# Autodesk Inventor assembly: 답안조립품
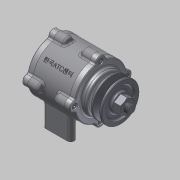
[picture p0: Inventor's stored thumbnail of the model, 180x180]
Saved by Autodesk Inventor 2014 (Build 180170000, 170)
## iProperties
Created: 2015-03
Part Number: 답안조립품
Document SubType Name: Assembly
Designer: MYHOME
Author: MYHOME
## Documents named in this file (11)
- C:\Documents and Settings\MYHOME\바탕 화면\450306V1026\답안조립품.iam
- C:\Documents and Settings\MYHOME\바탕 화면\450306V1026\본체.ipt
- C:\Documents and Settings\MYHOME\바탕 화면\450306V1026\축.ipt
- C:\Documents and Settings\MYHOME\바탕 화면\450306V1026\베어링 6204.ipt
- C:\Documents and Settings\MYHOME\바탕 화면\450306V1026\키(4 x 4 x 12).ipt
- C:\Documents and Settings\MYHOME\바탕 화면\450306V1026\커버2.ipt
- C:\Documents and Settings\MYHOME\바탕 화면\450306V1026\M 4 x 12.ipt
- C:\Documents and Settings\MYHOME\바탕 화면\450306V1026\커버.ipt
- C:\Documents and Settings\MYHOME\바탕 화면\450306V1026\오일실.ipt
- C:\Documents and Settings\MYHOME\바탕 화면\450306V1026\V벨트풀리.ipt
- C:\Documents and Settings\MYHOME\바탕 화면\450306V1026\너트 M12x1.25.ipt
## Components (14 placed, 6 different names)
1. KS B 2023 6204 - 20 x 47 x 14:1 — 각도:1
2. KS B 2023 6204 - 20 x 47 x 14:2 — 각도:2
3. KS B 1311 (I) 4 x 4 x 12:1
4. KS B 2804 D D - 20 32 8:1
5. 그루브 풀리1:1
6. KS B 1012 클래스 1 일반 - 미터 M12x1.25:1 — 각도:3
7. KS B 1003 - 미터 M 4 x 12:1
8. KS B 1003 - 미터 M 4 x 12:2
9. KS B 1003 - 미터 M 4 x 12:3
10. KS B 1003 - 미터 M 4 x 12:4
11. KS B 1003 - 미터 M 4 x 12:5
12. KS B 1003 - 미터 M 4 x 12:6
13. KS B 1003 - 미터 M 4 x 12:7
14. KS B 1003 - 미터 M 4 x 12:8
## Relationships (3: Angle 3)
- 각도:1 [Angle]: KS B 2023 6204 - 20 x 47 x 14:1
- 각도:2 [Angle]: KS B 2023 6204 - 20 x 47 x 14:2
- 각도:3 [Angle]: KS B 1012 클래스 1 일반 - 미터 M12x1.25:1
